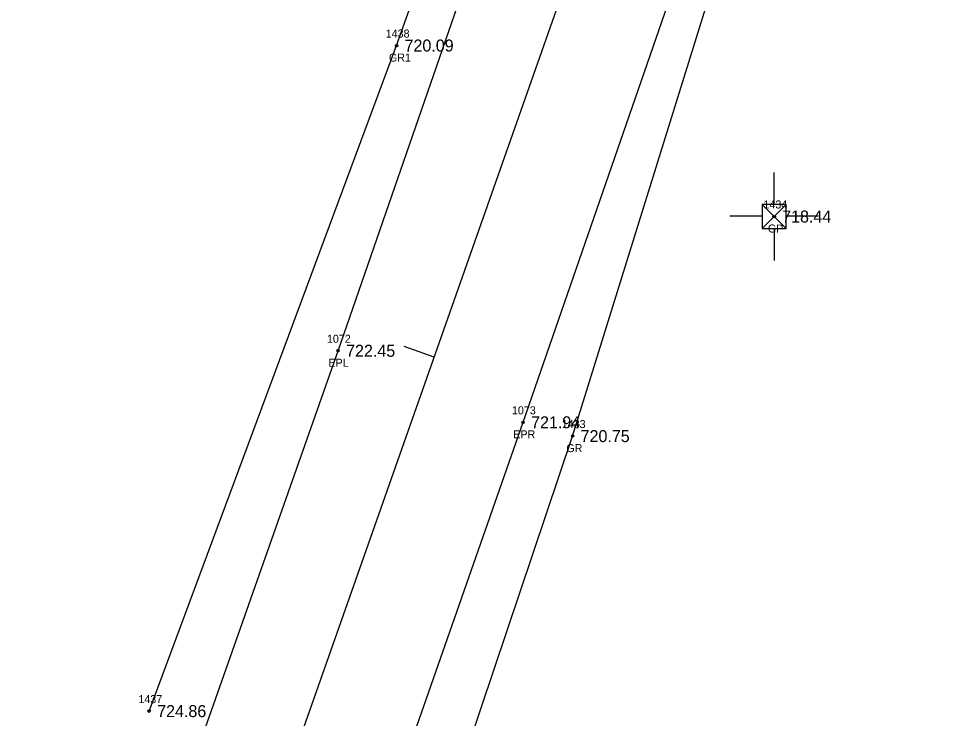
# Model space of a CAD drawing. Extents: x 1736563 to 1738032, y 1150548 to 1154248.
# Drawn here: x 1737322 to 1737439.5, y 1152510.8 to 1152598.1 of the extents above; entities that cross this region are included whole.
import ezdxf

# ---------------------------------------------------------------- set-up
doc = ezdxf.new("R2010")
doc.units = 0
for name, color, linetype in [('RD_EX_GuardRail', 7, 'Continuous'), ('RD_EX_GuardRail_txCode', 7, 'Continuous'), ('RD_EX_Road', 7, 'Continuous'), ('RD_EX_Road_txCode', 7, 'Continuous'), ('RD_EX_TX_GuardRail_ELEV', 7, 'Continuous'), ('RD_EX_TX_Road_ELEV', 7, 'Continuous'), ('RD_EX_TX_UT_ELEV', 7, 'Continuous'), ('RD_EX_UT', 7, 'Continuous'), ('RD_EX_UT_txCode', 7, 'Continuous'), ('RD_HC_Cl', 7, 'Continuous'), ('RD_HC_Data_Tic', 7, 'Continuous'), ('RD_SMD_Locator', 7, 'Continuous')]:
    doc.layers.add(name, color=color, linetype=linetype)

msp = doc.modelspace()

# ---------------------------------------------------------------- linework, layer by layer
at = {"layer": 'RD_EX_GuardRail'}
for points in [[(1737338.24, 1152511.65), (1737369.14, 1152594.73), (1737395.87, 1152669.44), (1737425.76, 1152754.51), (1737455.78, 1152858.18)], [(1737351.87, 1152429.26), (1737391.13, 1152545.98), (1737408.34, 1152601.39), (1737428.16, 1152658.66), (1737456.13, 1152738.69), (1737462.06, 1152749.07), (1737464.76, 1152758.57), (1737497.67, 1152845.09)]]:
    msp.add_lwpolyline(points, dxfattribs=at)
at = {"layer": 'RD_EX_Road'}
for points in [[(1736868.01, 1151157.6), (1736882.54, 1151196.52), (1736892.4, 1151226.58), (1736911.77, 1151279.81), (1736926.32, 1151321.94), (1736959.92, 1151418.27), (1736977.6, 1151467.57), (1736993.86, 1151514.24), (1737026.63, 1151607.21), (1737059.17, 1151698.64), (1737091.53, 1151790.84), (1737119.9, 1151870.3), (1737125.51, 1151887.21), (1737129.74, 1151897.31), (1737157.61, 1151979.19), (1737191.07, 1152073.18), (1737224.57, 1152167.62), (1737258.08, 1152262.33), (1737292.51, 1152359.5), (1737326.83, 1152457.35), (1737361.84, 1152556.63), (1737380.81, 1152611.37), (1737392.07, 1152607.38)], [(1737114.69, 1151782.27), (1737149.29, 1151879.88), (1737171.36, 1151942.06), (1737180.55, 1151968.4), (1737214.61, 1152064.48), (1737248.04, 1152159.34), (1737281.83, 1152253.71), (1737315.68, 1152350.56), (1737350.18, 1152448.39), (1737384.95, 1152547.7), (1737404.17, 1152603.14), (1737392.07, 1152607.38)]]:
    msp.add_lwpolyline(points, dxfattribs=at)
at = {"layer": 'RD_EX_UT'}
for p, q in [((1737416.31, 1152574.89), (1737416.31, 1152578.89)), ((1737417.81, 1152574.89), (1737414.81, 1152571.89)), ((1737414.81, 1152574.89), (1737417.81, 1152571.89)), ((1737417.81, 1152574.89), (1737414.81, 1152574.89)), ((1737414.81, 1152574.89), (1737414.81, 1152571.89)), ((1737417.81, 1152571.89), (1737417.81, 1152574.89)), ((1737414.79, 1152573.44), (1737410.79, 1152573.44)), ((1737417.83, 1152573.46), (1737421.84, 1152573.46)), ((1737414.81, 1152571.89), (1737417.81, 1152571.89)), ((1737416.31, 1152571.89), (1737416.31, 1152567.89))]:
    msp.add_line(p, q, dxfattribs=at)
at = {"layer": 'RD_HC_Cl'}
msp.add_line((1736879.96, 1151154.46), (1737935.1, 1154148.31), dxfattribs=at)
at = {"layer": 'RD_HC_Data_Tic'}
msp.add_line((1737373.85, 1152555.82), (1737370.08, 1152557.15), dxfattribs=at)
at = {"layer": 'RD_SMD_Locator'}
for centre in [(1737369.14, 1152594.73), (1737416.31, 1152573.39), (1737361.84, 1152556.63), (1737384.95, 1152547.7), (1737391.13, 1152545.98), (1737338.24, 1152511.65)]:
    msp.add_circle(centre, 0.15, dxfattribs=at)

# ---------------------------------------------------------------- texts
at = {"layer": 'RD_EX_GuardRail_txCode'}
for s, p in [('1438', (1737367.79, 1152595.73)), ('GR1', (1737368.19, 1152592.73)), ('1433', (1737389.78, 1152546.98)), ('GR', (1737390.35, 1152543.98)), ('1437', (1737336.9, 1152512.65))]:
    msp.add_text(s, height=1, dxfattribs=at).set_placement(p)
at = {"layer": 'RD_EX_Road_txCode'}
for s, p in [('1072', (1737360.45, 1152557.63)), ('EPL', (1737360.63, 1152554.63)), ('1073', (1737383.56, 1152548.7)), ('EPR', (1737383.72, 1152545.7))]:
    msp.add_text(s, height=1, dxfattribs=at).set_placement(p)
at = {"layer": 'RD_EX_TX_GuardRail_ELEV'}
for s, p in [('720.09', (1737370.14, 1152593.98)), ('720.75', (1737392.13, 1152545.23)), ('724.86', (1737339.24, 1152510.9))]:
    msp.add_text(s, height=1.5, dxfattribs=at).set_placement(p)
at = {"layer": 'RD_EX_TX_Road_ELEV'}
for s, p in [('722.45', (1737362.84, 1152555.88)), ('721.94', (1737385.95, 1152546.95))]:
    msp.add_text(s, height=1.5, dxfattribs=at).set_placement(p)
at = {"layer": 'RD_EX_TX_UT_ELEV'}
msp.add_text('718.44', height=1.5, dxfattribs=at).set_placement((1737417.31, 1152572.64))
at = {"layer": 'RD_EX_UT_txCode'}
for s, p in [('1434', (1737414.97, 1152574.39)), ('GP', (1737415.53, 1152571.39))]:
    msp.add_text(s, height=1, dxfattribs=at).set_placement(p)

doc.saveas('drawing.dxf')
